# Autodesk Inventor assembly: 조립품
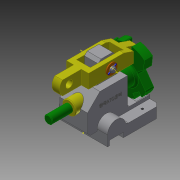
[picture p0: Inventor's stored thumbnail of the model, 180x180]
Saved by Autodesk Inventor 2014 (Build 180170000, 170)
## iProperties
Created: 2016-11
Part Number: 조립품
Document SubType Name: Assembly
Designer: USER
Author: USER
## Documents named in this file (8)
- C:\Users\USER\Desktop\461108V1028\조립품.iam
- C:\Users\USER\Desktop\461108V1028\본체.ipt
- C:\Users\USER\Desktop\461108V1028\부시.ipt
- C:\Users\USER\Desktop\461108V1028\분할대.ipt
- C:\Users\USER\Desktop\461108V1028\분할축.ipt
- C:\Users\USER\Desktop\461108V1028\와셔.ipt
- C:\Users\USER\Desktop\461108V1028\원통형핀.ipt
- C:\Users\USER\Desktop\461108V1028\클레비스핀.ipt
